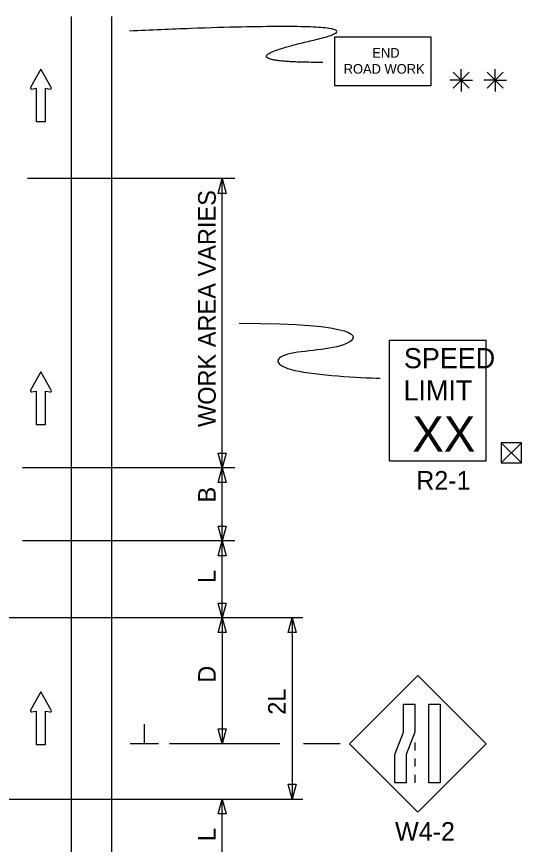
# Model space of a CAD drawing. Extents: x 16724 to 18475, y 7025 to 8210.
# Drawn here: x 16958.6 to 17159.2, y 7881.5 to 8210.4 of the extents above; entities that cross this region are included whole.
import ezdxf

# ---------------------------------------------------------------- set-up
doc = ezdxf.new("R2010")
doc.units = 0
for name, color, linetype in [('MT_SCRATCH_LEVEL_E', 7, 'Continuous'), ('PAVT_EDGE_EX', 7, 'Continuous'), ('TRAFFIC_SIGNS_PR', 7, 'Continuous'), ('TYPICAL_TEXT_DIMEN_PR', 7, 'Continuous')]:
    doc.layers.add(name, color=color, linetype=linetype)

msp = doc.modelspace()

# ---------------------------------------------------------------- linework, layer by layer
at = {"layer": 'MT_SCRATCH_LEVEL_E'}
for p, q in [((16968.25, 8189.53), (16964.14, 8182.29)), ((16972.4, 8182.29), (16968.25, 8189.53)), ((16964.62, 8181.61), (16966.4, 8181.92)), ((16966.4, 8181.92), (16966.4, 8168.67)), ((16970.14, 8168.67), (16970.14, 8181.92)), ((16970.14, 8181.92), (16971.92, 8181.61)), ((16966.4, 8168.67), (16970.14, 8168.67)), ((16968.25, 8069.2), (16964.14, 8061.96)), ((16972.4, 8061.96), (16968.25, 8069.2)), ((16964.62, 8061.28), (16966.4, 8061.59)), ((16966.4, 8061.59), (16966.4, 8048.33)), ((16970.14, 8048.33), (16970.14, 8061.59)), ((16970.14, 8061.59), (16971.92, 8061.28)), ((16966.4, 8048.33), (16970.14, 8048.33)), ((16968.25, 7942.06), (16964.14, 7934.82)), ((16972.4, 7934.82), (16968.25, 7942.06)), ((16964.62, 7934.13), (16966.4, 7934.45)), ((16966.4, 7934.45), (16966.4, 7921.19)), ((16970.14, 7921.19), (16970.14, 7934.45)), ((16970.14, 7934.45), (16971.92, 7934.13)), ((16966.4, 7921.19), (16970.14, 7921.19))]:
    msp.add_line(p, q, dxfattribs=at)
for centre, start, end in [((16964.55, 8182.07), 150.4248, 279.9638), ((16971.99, 8182.07), 260.0362, 29.7731), ((16964.55, 8061.73), 150.4248, 279.9638), ((16971.99, 8061.74), 260.0362, 29.7731), ((16964.55, 7934.59), 150.4248, 279.9638), ((16971.99, 7934.59), 260.0362, 29.7731)]:
    msp.add_arc(centre, 0.463, start, end, dxfattribs=at)
at = {"layer": 'PAVT_EDGE_EX'}
for p, q in [((16980.3, 8210.42), (16980.3, 7546.41)), ((16996.3, 8210.42), (16996.3, 7546.41))]:
    msp.add_line(p, q, dxfattribs=at)
at = {"layer": 'TRAFFIC_SIGNS_PR'}
for p, q in [((17106.73, 8081.82), (17145.13, 8081.82)), ((17106.73, 8033.82), (17106.73, 8081.82)), ((17145.13, 8033.82), (17145.13, 8081.82)), ((17106.73, 8033.82), (17145.13, 8033.82)), ((17118.03, 7948.63), (17090.88, 7921.48)), ((17145.18, 7921.48), (17118.03, 7948.63)), ((17116.78, 7921.97), (17116.78, 7918.77)), ((17090.88, 7921.48), (17118.03, 7894.33)), ((17118.03, 7894.33), (17145.18, 7921.48)), ((17116.78, 7915.57), (17116.78, 7912.37)), ((17116.78, 7909.17), (17116.78, 7905.97))]:
    msp.add_line(p, q, dxfattribs=at)
for points in [[(17084.96, 8182.97), (17123.36, 8182.97), (17123.36, 8202.17), (17084.96, 8202.17)], [(17116.78, 7937.22), (17116.78, 7926.03), (17113.44, 7917.15), (17113.44, 7905.97), (17108.95, 7905.97), (17108.95, 7917.15), (17112.29, 7926.03), (17112.29, 7937.22)], [(17126.92, 7937.22), (17126.92, 7905.97), (17122.43, 7905.97), (17122.43, 7937.22)]]:
    msp.add_lwpolyline(points, close=True, dxfattribs=at)
msp.add_open_spline([(17080.24, 8192.2), (17037.73, 8192.2), (17114.25, 8209.62), (17003.46, 8204.67)], degree=2, dxfattribs=at)
at = {"layer": 'TYPICAL_TEXT_DIMEN_PR'}
for p, q in [((17132.11, 8188.28), (17138.48, 8181.91)), ((17138.48, 8188.28), (17132.11, 8181.91)), ((17135.3, 8185.1), (17135.3, 8189.55)), ((17151.99, 8188.28), (17145.61, 8181.91)), ((17145.62, 8188.28), (17151.99, 8181.91)), ((17148.8, 8185.1), (17148.8, 8189.55)), ((17135.3, 8185.1), (17130.76, 8185.1)), ((17135.3, 8185.1), (17138.48, 8185.1)), ((17135.3, 8185.1), (17139.77, 8185.1)), ((17135.3, 8185.1), (17135.3, 8180.6)), ((17148.8, 8185.1), (17144.27, 8185.1)), ((17148.8, 8185.1), (17151.99, 8185.1)), ((17148.8, 8185.1), (17153.28, 8185.1)), ((17148.8, 8185.1), (17148.8, 8180.6)), ((17045.3, 8146.01), (16962.9, 8146.01)), ((17038.72, 8140.15), (17040.3, 8146.01)), ((17040.3, 8031.1), (17040.3, 8146.01)), ((17040.3, 8146.01), (17041.87, 8140.15)), ((17040.3, 8140.15), (17038.72, 8140.15)), ((17041.87, 8140.15), (17040.3, 8140.15)), ((17151.2, 8033.09), (17159.2, 8041.09)), ((17151.2, 8041.08), (17159.2, 8033.09)), ((17040.3, 8031.1), (17038.72, 8036.96)), ((17038.72, 8036.96), (17040.3, 8036.96)), ((17040.3, 8036.96), (17041.87, 8036.96)), ((17041.87, 8036.96), (17040.3, 8031.1)), ((17045.3, 8031.1), (16960.9, 8031.1)), ((17038.72, 8025.24), (17040.3, 8031.1)), ((17040.3, 8002.04), (17040.3, 8031.1)), ((17040.3, 8031.1), (17041.87, 8025.24)), ((17040.3, 8025.24), (17038.72, 8025.24)), ((17041.87, 8025.24), (17040.3, 8025.24)), ((17040.3, 8002.04), (17038.72, 8007.91)), ((17038.72, 8007.91), (17040.3, 8007.91)), ((17040.3, 8007.91), (17041.87, 8007.91)), ((17041.87, 8007.91), (17040.3, 8002.04)), ((17045.3, 8002.04), (16960.9, 8002.04)), ((17038.72, 7996.18), (17040.3, 8002.04)), ((17040.3, 7971.48), (17040.3, 8002.04)), ((17040.3, 8002.04), (17041.87, 7996.18)), ((17040.3, 7996.18), (17038.72, 7996.18)), ((17041.87, 7996.18), (17040.3, 7996.18)), ((17040.3, 7971.48), (17038.72, 7977.34)), ((17038.72, 7977.34), (17040.3, 7977.34)), ((17040.3, 7977.34), (17041.87, 7977.34)), ((17041.87, 7977.34), (17040.3, 7971.48)), ((17072.34, 7971.48), (16937.79, 7971.48)), ((17038.72, 7965.62), (17040.3, 7971.48)), ((17040.3, 7971.48), (17040.3, 7921.48)), ((17040.3, 7971.48), (17041.87, 7965.62)), ((17066.53, 7965.62), (17068.1, 7971.48)), ((17068.1, 7971.48), (17069.67, 7965.62)), ((17068.1, 7971.48), (17068.1, 7899.48)), ((17040.3, 7965.62), (17038.72, 7965.62)), ((17041.87, 7965.62), (17040.3, 7965.62)), ((17068.1, 7965.62), (17066.53, 7965.62)), ((17069.67, 7965.62), (17068.1, 7965.62)), ((17009.42, 7921.48), (17009.42, 7929.26)), ((17040.3, 7921.48), (17038.72, 7927.34)), ((17038.72, 7927.34), (17040.3, 7927.34)), ((17040.3, 7927.34), (17041.87, 7927.34)), ((17041.87, 7927.34), (17040.3, 7921.48)), ((17068.1, 7926.35), (17068.1, 7922.58)), ((17015.05, 7921.48), (17003.8, 7921.48)), ((17063.22, 7921.48), (17019.3, 7921.48)), ((17087.21, 7921.48), (17072.64, 7921.48)), ((17068.1, 7899.48), (17066.53, 7905.34)), ((17066.53, 7905.34), (17068.1, 7905.34)), ((17068.1, 7905.34), (17069.67, 7905.34)), ((17069.67, 7905.34), (17068.1, 7899.48)), ((16937.79, 7899.48), (17072.34, 7899.48)), ((17038.72, 7893.62), (17040.3, 7899.48)), ((17040.3, 7870.92), (17040.3, 7899.48)), ((17040.3, 7899.48), (17041.87, 7893.62)), ((17040.3, 7893.62), (17038.72, 7893.62)), ((17041.87, 7893.62), (17040.3, 7893.62))]:
    msp.add_line(p, q, dxfattribs=at)
msp.add_lwpolyline([(17151.2, 8041.08), (17151.2, 8033.09), (17159.2, 8033.09), (17159.2, 8041.09)], close=True, dxfattribs=at)
msp.add_open_spline([(17047.07, 8088.55), (17095.53, 8088.55), (17095.53, 8077.8), (17060.62, 8077.8), (17060.62, 8068.75), (17094.82, 8066.99), (17103.11, 8066.7)], degree=3, dxfattribs=at)

# ---------------------------------------------------------------- texts
at = {"layer": 'TRAFFIC_SIGNS_PR'}
for s, height, p in [('END', 3.831, (17099.96, 8194.1)), ('ROAD WORK', 3.831, (17088.57, 8187.72)), ('SPEED', 8, (17112.5, 8070.68)), ('LIMIT', 8, (17112.34, 8057.88)), ('XX', 14.031, (17115.84, 8037.58)), ('R2-1', 7.44, (17117.41, 8022.38)), ('W4-2', 7.44, (17108.99, 7882.89))]:
    msp.add_text(s, height=height, dxfattribs=at).set_placement(p)
at = {"layer": 'TYPICAL_TEXT_DIMEN_PR'}
for s, p in [('WORK AREA VARIES', (17037.74, 8047.32)), ('B', (17037.74, 8017.31)), ('L', (17037.74, 7985.34)), ('D', (17037.74, 7945.7)), ('2L', (17065.54, 7932.98)), ('L', (17037.74, 7882.77))]:
    msp.add_text(s, height=7, rotation=90, dxfattribs=at).set_placement(p)

doc.saveas('drawing.dxf')
